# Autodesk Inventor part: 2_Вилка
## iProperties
Created: 2009-12
Part Number: 2_Вилка
Document SubType Name: Modeling
Designer: Jeck
Density: 1 g/cm^3
Mass: 552.433 g
Surface Area: 685.99 cm^2
Volume: 552.433 cm^3
Author: Jeck
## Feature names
1. Выдавливание1 [Extrusion]
2. Выдавливание2 [Extrusion]
3. Выдавливание3 [Extrusion]
4. Выдавливание4 [Extrusion]
5. Выдавливание5 [Extrusion]
6. Отверстие1 [Hole]
7. Фаска1 [Chamfer]
8. Сопряжение1 [Fillet]
9. Сопряжение2 [Fillet]
10. Зеркальное отражение1 [Mirror]
11. Отверстие2 [Hole]
